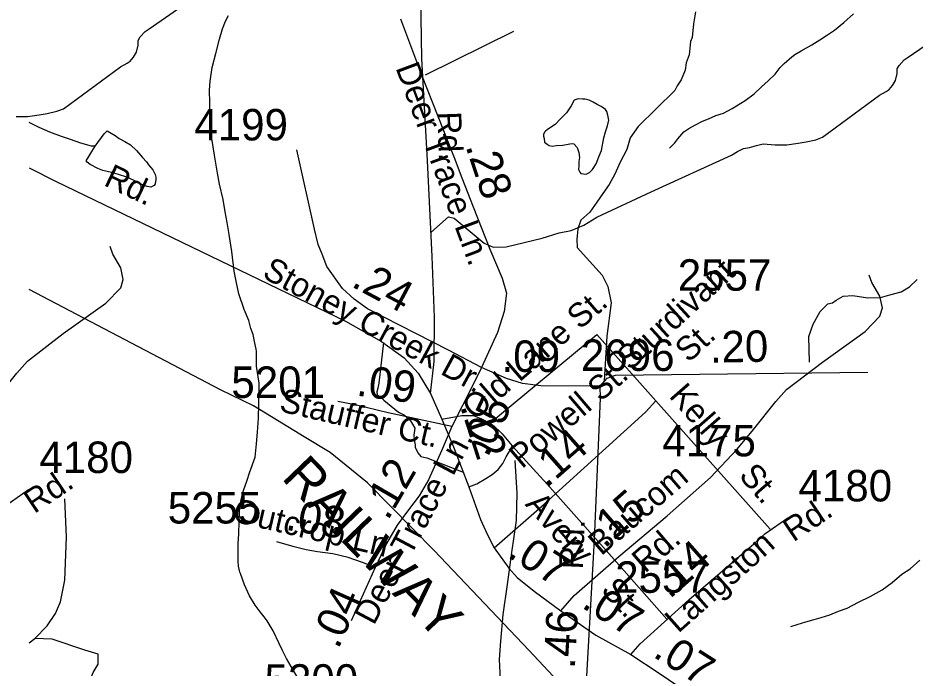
# Model space of a CAD drawing. Extents: x 2169602 to 2449496, y 721995 to 810662.
# Drawn here: x 2382070 to 2385634, y 768381 to 770964 of the extents above; entities that cross this region are included whole.
import ezdxf

# ---------------------------------------------------------------- set-up
doc = ezdxf.new("R2010")
doc.units = 0
doc.layers.add('Default', color=7, linetype='Continuous')

msp = doc.modelspace()

# ---------------------------------------------------------------- linework, layer by layer
at = {"layer": 'Default'}
for p, q in [((2383689.5, 770738.1), (2384039.6, 770912.4)), ((2384172.4, 769111.8), (2384033.7, 769264.2)), ((2384172.4, 769111.8), (2384438.9, 768812.5)), ((2384438.9, 768812.5), (2384648.3, 768575.7)), ((2383488.7, 768781), (2383394.1, 768568.5))]:
    msp.add_line(p, q, dxfattribs=at)
for points in [[(2383709.1, 769471.5), (2383723.4, 769599.3), (2383725.5, 769775.2), (2383715.1, 770016), (2383697.3, 770397.2), (2383674.3, 770803.5), (2383669, 771130.2), (2383656.5, 771498.8), (2383676.4, 772225.5), (2383682.6, 772640.1), (2383685.8, 772828.6), (2383669, 773134.4), (2383648.1, 773490.4), (2383624, 774045.4), (2383609.4, 774156.4), (2383582.2, 774250.6), (2383534, 774363.7)], [(2382062.5, 770572.6), (2382108.5, 770572.8), (2382154.4, 770579.1), (2382186.3, 770585.2), (2382224.3, 770593.3), (2382250.3, 770603.5), (2382477.5, 770770.5), (2382503.4, 770784.6), (2382515.3, 770792.5), (2382529.2, 770808.6), (2382541.1, 770828.8), (2382547, 770856.7), (2382547, 770874.6), (2382554.9, 770888.7), (2382574.7, 770910.9), (2382590.7, 770921), (2382704.3, 770999.4)], [(2383183.2, 768339.6), (2383155.1, 768387.3), (2383137, 768419.3), (2383120.6, 768451.3), (2383106.9, 768481.4), (2383084.3, 768529), (2383060.4, 768569.1), (2383048.5, 768584.7), (2383032.3, 768604.6), (2383012, 768630.8), (2382989.8, 768668.6), (2382969.9, 768712.6), (2382953.5, 768756.5), (2382951.5, 768762.5), (2382945.7, 768786.5), (2382945.3, 768804.3), (2382945.3, 768840.5), (2382944.9, 768876.2), (2382947.2, 768914.4), (2382948.6, 768962.4), (2382950.6, 769004.4), (2382956.6, 769050.5), (2382966.4, 769086.3), (2382980.2, 769128.4), (2382990, 769156.6), (2383011.8, 769218.6), (2383017.3, 769272.5), (2383021.2, 769318.6), (2383025.1, 769374.7), (2383026.7, 769430.5), (2383028.4, 769484.6), (2383028.4, 769512.6), (2383018.1, 769580.7), (2383017.9, 769640.3), (2383015.9, 769648.3), (2383009.7, 769678.5), (2383003.8, 769706.1), (2382995.3, 769730.1), (2382987.1, 769762.2), (2382968.9, 769806.3), (2382947, 769868), (2382938.6, 769911.9), (2382928.3, 769958.1), (2382920.1, 770036), (2382909.6, 770103.7), (2382901.6, 770151.9), (2382893.2, 770193.8), (2382885.4, 770243.6), (2382870.7, 770303.4), (2382862.9, 770347.6), (2382850.6, 770419.3), (2382840.3, 770485.3), (2382838.1, 770507.6), (2382834.2, 770573.4), (2382831.7, 770627.4), (2382831.5, 770677.3), (2382833.2, 770713.5), (2382840.9, 770767.1), (2382856.7, 770823.5), (2382870.7, 770879.4), (2382882.4, 770921.5), (2382894.1, 770951.3), (2382906.4, 770973.4)], [(2384761.7, 770988.4), (2384753.9, 770940.4), (2384748.2, 770886.3), (2384742.3, 770870.2), (2384736.6, 770818.4), (2384724.8, 770786.2), (2384720.8, 770756.3), (2384705, 770718.2), (2384689.1, 770694.1), (2384679.1, 770676.1), (2384533.8, 770533.5), (2384502.1, 770487.4), (2384488.4, 770441.3), (2384462.5, 770391.2), (2384440.8, 770343.3), (2384418.9, 770303.1), (2384393, 770267), (2384369.3, 770232.9), (2384341.5, 770192.7), (2384305.6, 770160.6), (2384293.7, 770126.7), (2384289.9, 770084.6), (2384292, 770052.5), (2384391.4, 769942.7), (2384413.5, 769896.8), (2384427, 769831.8), (2384409.6, 769700.3), (2384398.5, 769522.8)], [(2384658.1, 770447.2), (2384679.6, 770467.5), (2384691.7, 770483.5), (2384715.9, 770511.5), (2384735.2, 770525.5), (2384759.4, 770537.7), (2384789.4, 770553.9), (2384813.1, 770564.1), (2384843.1, 770576.2), (2384873.2, 770586.2), (2384906.8, 770604.2), (2384959.1, 770636.5), (2384994.8, 770662.7), (2385024.5, 770690.7), (2385050.8, 770715.1), (2385078.5, 770741), (2385098.6, 770767.1), (2385113.9, 770783), (2385144.3, 770809.3), (2385156, 770819.2), (2385181.8, 770833.6), (2385223.7, 770857.7), (2385255.6, 770878), (2385285.6, 770897.8), (2385313.7, 770915.9), (2385351.4, 770946.3), (2385389.1, 770980.4)], [(2383589.2, 770961.4), (2383672.6, 770738), (2383803.1, 770410), (2383833.6, 770328.8), (2383878.3, 770213.6), (2383944.1, 770045.5), (2383993.5, 769930.2), (2384011.1, 769870.3), (2384001.7, 769798.6), (2383974.7, 769714.6), (2383911.8, 769575.2)], [(2383710.6, 770112.4), (2383779.9, 770173.8), (2383802.8, 770168.9), (2383922.4, 770069.9), (2383957.4, 770053), (2384009.3, 770055.4), (2384152, 770089.9), (2384220, 770110.1), (2384268, 770120.3), (2384317.8, 770140.5), (2384369.7, 770172.8), (2384585.1, 770273.6), (2384904.5, 770419.1), (2384928.4, 770433.2), (2384952.4, 770445.3), (2384976.3, 770449.4), (2385004.3, 770457.5), (2385030.2, 770463.5), (2385078.3, 770459.7), (2385124.3, 770460), (2385170.2, 770466.3), (2385202.1, 770472.4), (2385240.1, 770480.4), (2385266.1, 770490.7), (2385493.3, 770657.7), (2385519.2, 770671.7), (2385531.1, 770679.7), (2385545.1, 770695.8), (2385556.9, 770715.9), (2385562.9, 770743.8), (2385562.8, 770761.8), (2385570.7, 770775.9), (2385590.6, 770798), (2385606.6, 770808.1), (2385720.2, 770886.6)], [(2384403.6, 770600.3), (2384387.6, 770612.1), (2384371.6, 770620.2), (2384355.4, 770629.9), (2384339.2, 770638), (2384323.4, 770641.7), (2384313.5, 770641.9), (2384295.1, 770643.5), (2384279.7, 770637.7), (2384267.6, 770615.6), (2384249.6, 770587.5), (2384225.8, 770563.5), (2384203.6, 770541.3), (2384189.7, 770531.3), (2384172.1, 770519.3), (2384165.7, 770515), (2384162.2, 770511.1), (2384157.9, 770501.2), (2384157.7, 770495.1), (2384160, 770485.1), (2384162.2, 770471), (2384172.5, 770463.3), (2384180.5, 770457.3), (2384192, 770455.5), (2384210.2, 770457.2), (2384234.2, 770459.2), (2384262.1, 770463.5), (2384272.3, 770465.6), (2384278.3, 770463.5), (2384292.2, 770449.7), (2384298.2, 770429.7), (2384300.4, 770409.9), (2384298.6, 770393.5), (2384298.6, 770375.7), (2384296.7, 770361.8), (2384302.7, 770351.9), (2384306.8, 770345.7), (2384326.9, 770343.8), (2384341, 770349.8), (2384352.3, 770361.9), (2384366.7, 770384.1), (2384378.1, 770411.9), (2384388, 770438), (2384398, 770488), (2384404.2, 770512.2), (2384412, 770536.2), (2384417.7, 770558.4), (2384413.4, 770578.1), (2384409.3, 770592.1), (2384403.6, 770600.3)], [(2382376.8, 770455.5), (2382362.7, 770455.2), (2382320.4, 770467.3), (2382279, 770480.8), (2382242.7, 770492.8), (2382196.4, 770510.8), (2382154.8, 770528.4), (2382114, 770549.2)], [(2382376.8, 770455.5), (2382412.5, 770503.7), (2382424.6, 770515.6), (2382456.4, 770497.8), (2382472.4, 770485.7), (2382494.5, 770473.8), (2382516.5, 770459.9), (2382540.5, 770438), (2382565.3, 770410.4), (2382580.9, 770392.2), (2382589.1, 770380.4), (2382605.3, 770360.5), (2382615.5, 770342.3), (2382617.2, 770332.3), (2382617.4, 770322.6), (2382615.1, 770304.7), (2382611.6, 770298.3), (2382603.2, 770294.3), (2382597.5, 770292.4), (2382583.7, 770294.4), (2382567.5, 770300.1), (2382531, 770318.2), (2382503.1, 770331.7), (2382469.1, 770341.7), (2382441.2, 770349.6), (2382407.2, 770357.6), (2382387.3, 770365.5), (2382356.7, 770381.4), (2382345.3, 770391.3), (2382341.2, 770397.2), (2382351, 770413.2), (2382362.9, 770433.3), (2382376.8, 770455.5)], [(2383911.8, 769575.2), (2383780.2, 769644.5), (2383458.8, 769809.1), (2383405.9, 769846.8), (2383360, 769889.1), (2383296.6, 769976.1), (2383278.1, 770025.8), (2383262.3, 770064.6), (2383248.2, 770124.5), (2383177.7, 770439.9)], [(2382114, 770368.7), (2382221.1, 770314.5), (2383371.1, 769759.5), (2383514.9, 769678.9), (2383603.9, 769613.9), (2383660.4, 769553.2), (2383709.1, 769471.5)], [(2381805.3, 769251.4), (2381911, 769364.5), (2381975.8, 769442), (2382065.8, 769552.9), (2382107.7, 769601.1), (2382250, 769710), (2382419.5, 769831.5), (2382478.1, 769892.2), (2382488.6, 769925.7), (2382478.1, 769971.8), (2382446.7, 770026.2), (2382436.2, 770055.6)], [(2384821.1, 769138.5), (2384926.8, 769251.6), (2384991.7, 769329.1), (2385081.6, 769440.1), (2385123.5, 769488.3), (2385265.8, 769597.2), (2385435.3, 769718.7), (2385493.9, 769779.4), (2385504.4, 769812.9), (2385493.9, 769859), (2385462.5, 769913.4), (2385452.1, 769942.7)], [(2385306.4, 769833), (2385320.6, 769843.1), (2385348.6, 769859.4), (2385386.6, 769861.4), (2385446.6, 769851.8), (2385496.5, 769854), (2385534.5, 769864.2), (2385578.5, 769876.3), (2385612.3, 769896.4), (2385642.3, 769924.6)], [(2384887.9, 767663.1), (2384856.4, 767687.8), (2384776.2, 767753.4), (2384707.8, 767825), (2384635.4, 767892.7), (2384468.8, 768057.9), (2384099.3, 768452.2), (2383723.7, 768848.4), (2383550.9, 769023.7), (2383458.6, 769117.2), (2383310.1, 769238.4), (2383207.7, 769300.1), (2383101.5, 769365.4), (2383005.3, 769423), (2382875.2, 769486.4), (2382114, 769885.3)], [(2385215.3, 769596), (2385212.5, 769698.4), (2385229.1, 769748.2), (2385256.8, 769798), (2385287.2, 769828.5), (2385306.4, 769833)], [(2383945.3, 769353.8), (2384369.8, 769706.7)], [(2384369.8, 769706.7), (2384603.7, 769442.7)], [(2383522.5, 769674.6), (2383503.4, 769513.4), (2383499.4, 769493.5), (2383495.5, 769479.3), (2383497.5, 769467.5), (2383509.5, 769459.5), (2383523.6, 769445.6), (2383581.8, 769397.8), (2383605.8, 769385.9), (2383630, 769364), (2383638.1, 769350), (2383646.1, 769334.1), (2383642.2, 769306.2), (2383644.2, 769288.1), (2383648.4, 769268), (2383648.4, 769258.2), (2383654.5, 769246.1), (2383658.5, 769236.2), (2383670.6, 769222.2), (2383694.5, 769216.3), (2383838.7, 769160)], [(2383911.8, 769575.2), (2383877.2, 769505.4), (2383794.3, 769341.2)], [(2384383.2, 769500.7), (2384146.8, 769502.3), (2384074, 769511.7), (2384010.5, 769531.7), (2383911.8, 769575.2)], [(2384383.2, 769500.7), (2384410.3, 769533.4), (2384443.9, 769544.6), (2385446.2, 769557.1)], [(2383709.1, 769471.5), (2383754.6, 769370), (2383800.6, 769260), (2383860.8, 769101.9), (2383907.9, 768971), (2383933.8, 768912.9), (2383961.5, 768859)], [(2383962.9, 767123.6), (2384159.1, 767588.5), (2384280.5, 767894.3), (2384305.6, 767999), (2384318.2, 768137.2), (2384360, 768891.2), (2384384.1, 769453), (2384383.2, 769500.7)], [(2383794.3, 769341.2), (2383540.4, 769395.3), (2383410.2, 769427.5), (2383340.6, 769440)], [(2384563.2, 769398.2), (2384603.7, 769442.7)], [(2384603.7, 769442.7), (2385058.1, 768933.4)], [(2383754.6, 769370), (2383833.5, 769385), (2383879.2, 769385.3), (2383911.3, 769371.5), (2383945.3, 769353.8), (2383977.4, 769327.9), (2383993.5, 769312), (2384033.7, 769264.2)], [(2383961.5, 768859), (2384161.9, 769033.8), (2384563.2, 769398.2)], [(2383794.3, 769341.2), (2383752.3, 769243.9), (2383700.9, 769129.4), (2383664, 769066), (2383621.7, 769009.3), (2383576.9, 768948.5), (2383534.7, 768875.9), (2383488.7, 768781)], [(2383860.8, 769101.9), (2383892.4, 769113.5), (2383928.4, 769133.8), (2383954.4, 769149.8), (2383978.2, 769169.9), (2383996.1, 769194), (2384010, 769220.1), (2384021.8, 769240), (2384033.7, 769264.2)], [(2384043.7, 769205.7), (2384052.3, 769075.9), (2384048.9, 768967.8), (2384031.4, 768839.8), (2384013.9, 768713.8), (2383996.4, 768593.7), (2383986.9, 768487.7), (2383981.2, 768415.7), (2383985.5, 768335.8)], [(2384226.8, 768608.7), (2384279.1, 768669.4), (2384457, 768824.4), (2384649.5, 768985.7), (2384821.1, 769138.5)], [(2381488.7, 768547.7), (2381525.9, 768590.6), (2381719.5, 768765.5), (2381977.4, 768987.5), (2382021.4, 769027.3), (2382112.4, 769091.2)], [(2382137.1, 768498.9), (2382186.6, 768548.5), (2382219.7, 768598), (2382239.5, 768644.3), (2382256, 768730.2), (2382262.6, 768902), (2382256, 769054)], [(2384504.6, 768434.9), (2384541.7, 768477.8), (2384735.3, 768652.7), (2384993.2, 768874.7), (2385037.2, 768914.5), (2385128.2, 768978.3)], [(2383488.7, 768781), (2383438.7, 768800.7), (2383381.6, 768820.3), (2383320.9, 768834.6), (2383260.2, 768843.5), (2383215.6, 768850.7), (2383167.4, 768863.2), (2383097.8, 768882.8)], [(2383961.5, 768859), (2384020.6, 768778.3), (2384053.1, 768741.7), (2384121.1, 768686.2), (2384226.8, 768608.7)], [(2385140, 768546.2), (2385166, 768554), (2385199.9, 768564.3), (2385233.9, 768574.6), (2385261.6, 768582.6), (2385295.6, 768592.8), (2385329.9, 768606.7), (2385363.7, 768619), (2385409.4, 768643.3), (2385455.2, 768665.6), (2385503.3, 768691.6), (2385543.1, 768721.7), (2385580.9, 768753.7), (2385614.7, 768776.1), (2385652.8, 768810.2)], [(2384226.8, 768608.7), (2384365.4, 768512.4), (2384504.6, 768434.9)], [(2382114, 768482), (2382137.1, 768498.9)], [(2382114, 768219.7), (2382150.3, 768218), (2382236.2, 768228), (2382302.2, 768257.7), (2382341.9, 768297.3), (2382368.3, 768363.4), (2382388.1, 768396.5), (2382388.1, 768436.1), (2382335.3, 768452.6), (2382206.5, 768495.6), (2382137.1, 768498.9)], [(2384504.6, 768434.9), (2384617.1, 768360.5), (2384769.8, 768257.9)]]:
    msp.add_lwpolyline(points, dxfattribs=at)

# ---------------------------------------------------------------- texts
for s, height, rotation, p in [('Deer Trace Ln.', 95, 290.4246, (2383569.1, 770766.6)), ('Rd.', 95, 271.9489, (2383736, 770591.1)), ('.28', 125, 288.1623, (2383847.3, 770455)), ('Rd.', 95, 334.5762, (2382406.5, 770301.1)), ('Stoney Creek Dr.', 95, 331.5206, (2383036.1, 769935.8)), ('.24', 125, 331.8339, (2383390, 769899.5)), ('Sturdivant', 95, 42.3711, (2384502.4, 769559.8)), ('Old Lane St.', 95, 40.9068, (2383886.2, 769362.5)), (' St.', 95, 42.3711, (2384708.2, 769567.7)), ('.20', 125, 1.1132, (2384819.7, 769594.2)), ('.09', 125, 359.8878, (2383991.2, 769558.2)), ('.09', 125, 352.2159, (2383411.4, 769464.4)), ('Powell St.', 95, 40.476, (2384072.3, 769170.5)), ('Kelly', 95, 311.1373, (2384653.1, 769460.4)), ('Stauffer Ct.', 95, 346.8959, (2383104.5, 769402.3)), ('.05', 125, 64.8894, (2383935.9, 769214.3)), ('.12', 125, 287.8797, (2383825.7, 769421.8)), ('.14', 125, 41.3782, (2384170.2, 769094.8)), ('Deer Trace Ln.', 95, 62.0434, (2383483.9, 768547.9)), ('RAILWAY', 150, 313.9414, (2383113.4, 769134.7)), ('.12', 125, 59.8214, (2383539.3, 768964.2)), ('St.', 95, 311.1373, (2384930.2, 769143.5)), ('Rd.', 95, 33.927, (2382134.7, 768992.6)), ('Baucom', 95, 40.674, (2384387.1, 768824.7)), ('.15', 125, 41.3782, (2384399.7, 768853.5)), ('Outcrop Ln', 95, 346.8959, (2382918.5, 768964.7)), ('.08', 125, 350.9046, (2383129.4, 768931)), ('Avery', 95, 310.6754, (2384082, 769030.5)), ('Rd.', 95, 33.927, (2385150.5, 768879.8)), ('Rd.', 95, 87.6918, (2384314.4, 768772.5)), ('Rd.', 95, 40.674, (2384560.5, 768755.5)), ('Langston', 95, 41.6252, (2384693.1, 768517)), ('.07', 125, 327.4651, (2384010.2, 768825.7)), ('.14', 125, 41.3782, (2384658.6, 768652.9)), (' St.', 95, 313.2282, (2384357.9, 768713)), ('.04', 125, 66.0041, (2383342.6, 768453.2)), ('.07', 125, 327.4651, (2384305, 768624.3)), ('.46', 125, 86.8224, (2384282.2, 768376.6)), ('.07', 125, 327.4651, (2384588.3, 768429))]:
    msp.add_text(s, height=height, rotation=rotation, dxfattribs=at).set_placement(p)
for s, p in [('4199', (2382770.7, 770477.7)), ('2557', (2384691.4, 769880.5)), ('2696', (2384306.7, 769561.9)), ('5201', (2382917.7, 769454.6)), ('4175', (2384629.8, 769222.5)), ('4180', (2382155.2, 769156.2)), ('4180', (2385171, 769043.4)), ('5255', (2382665.1, 768955.6)), ('2557', (2384442.7, 768680.2)), ('5200', (2383049.6, 768271.4))]:
    msp.add_text(s, height=125, dxfattribs=at).set_placement(p)

doc.saveas('drawing.dxf')
